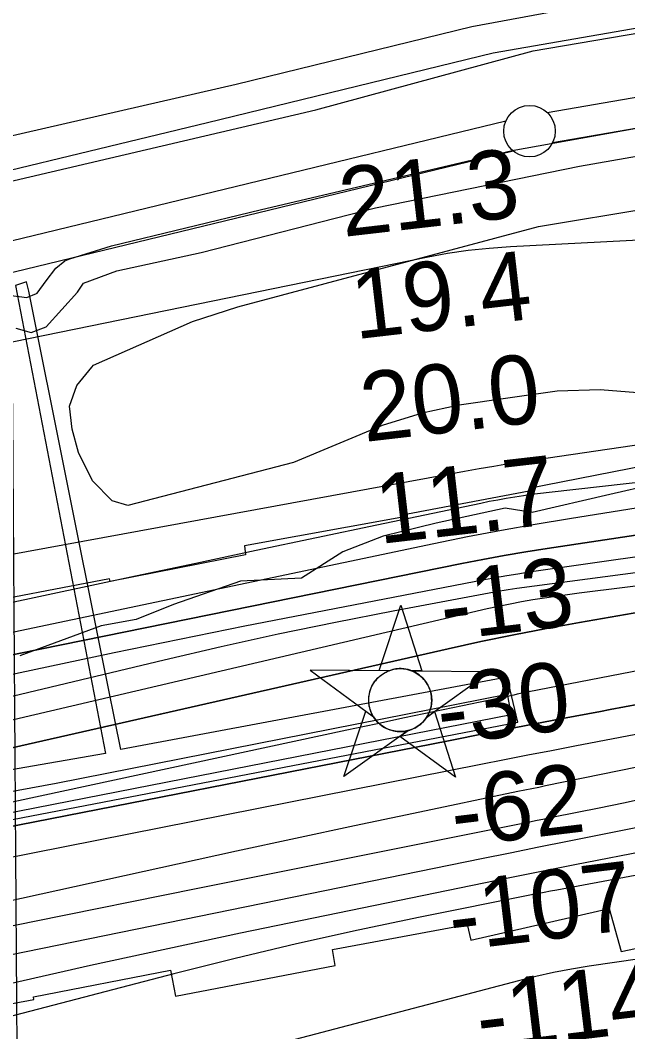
# Model space of a CAD drawing. Extents: x 3508733 to 3546731, y 546897 to 572481.
# Drawn here: x 3518107 to 3518696, y 565606 to 566587 of the extents above; entities that cross this region are included whole.
import ezdxf

# ---------------------------------------------------------------- set-up
doc = ezdxf.new("R2010")
doc.units = 0
for name, color, linetype in [('V-CHAN-DOCK', 7, 'Continuous'), ('V-CHAN-NAID', 7, 'Continuous'), ('V-FLOD-BASE', 7, 'Continuous'), ('V-GRID-MAJR', 7, 'Continuous'), ('V-LEVE-TOET', 7, 'Continuous'), ('V-RIVR-EDGE', 7, 'Continuous'), ('V-RIVR-RANG', 7, 'Continuous'), ('V-ROAD-CNTR', 7, 'Continuous'), ('V-RRAP-RVMT', 7, 'Continuous'), ('V-SITE-STRC', 7, 'Continuous'), ('V-SITE-VEGE', 7, 'Continuous'), ('V-SURV-LINE', 7, 'Continuous'), ('V-TOPO-DPTH', 7, 'Continuous'), ('V-TOPO-MAJR', 7, 'Continuous'), ('V-TOPO-MINR', 7, 'Continuous'), ('V-TOPO-SHOR', 7, 'Continuous'), ('V-TOPO-WATR', 7, 'Continuous')]:
    doc.layers.add(name, color=color, linetype=linetype)

msp = doc.modelspace()

# ---------------------------------------------------------------- linework, layer by layer
at = {"layer": 'V-CHAN-DOCK'}
for points in [[(3518186.52, 565967.83), (3518114.83, 566324.4), (3518112.73, 566333.57), (3518102.12, 566329.91), (3518103.69, 566321.76), (3518189.4, 565876.06), (3518096.29, 565859.93), (3518076.82, 565959.55), (3517887.02, 565919.49), (3517887.88, 565914.27)], [(3517959.44, 565784.97), (3518589.39, 565906.48), (3518579.11, 565950.09), (3518204.17, 565880.03), (3518186.52, 565967.83), (3518114.83, 566324.4), (3518112.73, 566333.57), (3518102.12, 566329.91)], [(3518103.69, 566321.76), (3518189.4, 565876.06), (3518096.29, 565859.93)], [(3517131.86, 565639.29), (3517144.94, 565644.79), (3517155.86, 565644.73), (3517155.88, 565648.11), (3517227.94, 565658.8), (3517227.93, 565657.27), (3517239.93, 565657.2), (3517239.95, 565660.69), (3517311.61, 565672.83), (3517312.53, 565658.83), (3517659.16, 565725.77), (3517657.93, 565735.21), (3517765.2, 565758.26), (3517782.37, 565748.33), (3517807.13, 565753.78), (3517812.95, 565767.98), (3517923.78, 565788.1), (3517926.79, 565778.68), (3517959.44, 565784.97), (3518589.39, 565906.48), (3518579.11, 565950.09), (3518204.17, 565880.03), (3518186.52, 565967.83)]]:
    msp.add_lwpolyline(points, dxfattribs=at)
at = {"layer": 'V-CHAN-NAID'}
for points in [[(3518464.43, 565956.3), (3518454.85, 565956.37), (3518475.97, 566019.86), (3518496.2, 565956.08), (3518486.61, 565956.15), (3518485.03, 565956.73), (3518482.94, 565957.35), (3518480.9, 565957.8), (3518478.86, 565958.1), (3518477.69, 565958.22), (3518476.16, 565958.3), (3518474.44, 565958.3), (3518473.07, 565958.23), (3518471.16, 565958.03), (3518469.8, 565957.81), (3518468.01, 565957.42), (3518466.48, 565957), (3518465.45, 565956.67)], [(3518464.43, 565956.3), (3518387.94, 565956.85), (3518449.51, 565911.45), (3518448.39, 565913.36), (3518447.58, 565914.98), (3518446.76, 565916.95), (3518446.06, 565919.01), (3518445.7, 565920.33), (3518445.34, 565921.96), (3518445.09, 565923.4), (3518444.9, 565925), (3518444.8, 565926.73), (3518444.78, 565928.32), (3518444.89, 565930.39), (3518445.07, 565932.01), (3518445.47, 565934.21), (3518445.95, 565936.13), (3518446.55, 565938.02), (3518447.2, 565939.7), (3518447.93, 565941.29), (3518448.75, 565942.82), (3518449.81, 565944.56), (3518450.84, 565946.03), (3518451.84, 565947.3), (3518452.84, 565948.44), (3518454.15, 565949.78), (3518455.2, 565950.75), (3518456.92, 565952.14), (3518458.13, 565953.01), (3518459.82, 565954.08), (3518461.55, 565955.03), (3518462.99, 565955.71)], [(3518486.61, 565956.15), (3518563.1, 565955.6), (3518500.9, 565911.08), (3518501.81, 565912.57), (3518502.79, 565914.42), (3518503.5, 565916), (3518504.24, 565917.96), (3518504.79, 565919.74), (3518505.18, 565921.38), (3518505.54, 565923.39), (3518505.73, 565924.97), (3518505.85, 565927.17), (3518505.82, 565929.23), (3518505.64, 565931.45), (3518505.37, 565933.21), (3518504.88, 565935.44), (3518504.24, 565937.58), (3518503.49, 565939.57), (3518502.84, 565941.01), (3518501.83, 565942.92), (3518500.77, 565944.65), (3518499.56, 565946.35), (3518498.3, 565947.89), (3518497.03, 565949.25), (3518495.39, 565950.79), (3518493.65, 565952.2), (3518491.97, 565953.37), (3518490.08, 565954.51), (3518488.61, 565955.27)], [(3518482.87, 565898.18), (3518420.66, 565853.65), (3518441.79, 565917.14), (3518449.51, 565911.45), (3518450.14, 565910.48), (3518451.52, 565908.62), (3518452.74, 565907.21), (3518454.2, 565905.71), (3518455.59, 565904.45), (3518457.05, 565903.3), (3518458.45, 565902.31), (3518460.13, 565901.28), (3518461.84, 565900.36), (3518463.63, 565899.55), (3518465.08, 565899), (3518466.71, 565898.47), (3518468.93, 565897.9), (3518470.46, 565897.62), (3518472.49, 565897.36), (3518474.03, 565897.26), (3518475.89, 565897.23), (3518477.58, 565897.31), (3518479.29, 565897.49), (3518481.19, 565897.8)], [(3518500.9, 565911.08), (3518508.69, 565916.66), (3518528.92, 565852.89), (3518475.07, 565892.6), (3518482.87, 565898.18), (3518484.53, 565898.65), (3518486.14, 565899.21), (3518488.3, 565900.13), (3518490.04, 565901.01), (3518491.9, 565902.12), (3518493.64, 565903.34), (3518495.19, 565904.58), (3518496.48, 565905.75), (3518497.87, 565907.17), (3518499.07, 565908.57), (3518500.19, 565910.04)]]:
    msp.add_lwpolyline(points, close=True, dxfattribs=at)
msp.add_circle((3518475.32, 565927.77), 30.54, dxfattribs=at)
at = {"layer": 'V-FLOD-BASE'}
msp.add_lwpolyline([(3518095.45, 566320.82), (3518113.13, 566318.56), (3518122.53, 566322.15), (3518123.12, 566322.74), (3518131.88, 566334.58), (3518141.23, 566347), (3518150.03, 566354.12), (3518154.73, 566355.91), (3518195.29, 566368.52), (3518339.39, 566403.52), (3518584.06, 566460.9), (3518796.46, 566499.24), (3518997.08, 566535.75), (3519002.97, 566536.37), (3519010.62, 566537), (3519058.86, 566547.3)], dxfattribs=at)
at = {"layer": 'V-GRID-MAJR'}
msp.add_spline([(3518190.88, 552332.11), (3518151.22, 558391.11), (3518111.55, 564452.04), (3518071.88, 570512.99), (3518071.87, 570514.91)], degree=3, dxfattribs=at)
at = {"layer": 'V-LEVE-TOET'}
for points in [[(3517635.06, 566318.51), (3517790.52, 566358.34), (3518043.75, 566418.79), (3518393.57, 566500.44), (3518604.36, 566557.69), (3518815.27, 566593.71), (3518991.43, 566623.05), (3519136.95, 566645.72)], [(3518451.29, 566405.29), (3518649.32, 566445.87), (3518756.28, 566464.73), (3518959.03, 566502.97), (3518976.05, 566509.54), (3518987.22, 566510.79), (3518994.89, 566507.89), (3519007.84, 566506.2), (3519020.16, 566511.57), (3519038.38, 566515.79), (3519138.88, 566534.03)], [(3518102.51, 566288.54), (3518117.24, 566284.5), (3518131.92, 566289.88), (3518162.31, 566323.6), (3518168.15, 566332.46), (3518200.43, 566344.41), (3518282.11, 566361.95), (3518451.29, 566405.29)]]:
    msp.add_lwpolyline(points, dxfattribs=at)
at = {"layer": 'V-RIVR-EDGE'}
msp.add_lwpolyline([(3518721.14, 566137.05), (3518678.84, 566127.35), (3518603.43, 566109.77), (3518577.1, 566114.12), (3518510.27, 566099.58), (3518458.77, 566086.84), (3518419.52, 566071.62), (3518379.63, 566045.99), (3518320.19, 566043.07), (3518255.18, 566020.56), (3518219, 566005.94), (3518185.28, 565999.9), (3518106.17, 565970.68)], dxfattribs=at)
at = {"layer": 'V-ROAD-CNTR'}
msp.add_lwpolyline([(3519712.95, 566785.8), (3519437.37, 566738.42), (3518962.97, 566657.35), (3518684.89, 566607.1), (3518544.78, 566581.1), (3518316.18, 566525.03), (3517942.23, 566439.4), (3517865.78, 566419.68)], dxfattribs=at)
at = {"layer": 'V-RRAP-RVMT'}
for points in [[(3519304.25, 566038.12), (3519163.73, 566010.36), (3519164.23, 566005.68), (3519054.87, 565985.48), (3519054.36, 565988.99), (3518927.29, 565964.84), (3518914.72, 566031.29), (3518778.07, 566005.97), (3518747.03, 566161.85), (3518600.25, 566133.12), (3518600.36, 566130.45), (3518475.67, 566106.91)], [(3518475.67, 566106.91), (3518475.97, 566104.92), (3518324.08, 566077.35), (3518325.21, 566068.76), (3518193.96, 566042.75), (3518193.27, 566045.42), (3518047.8, 566017.61)], [(3518678.12, 565725.59), (3518689.72, 565683.99), (3518828.52, 565712.86), (3518827.15, 565719.64), (3518969, 565747.04), (3518967.17, 565756.08), (3519092.65, 565780.26), (3519092.36, 565782.6), (3519217.74, 565805.53), (3519217.3, 565808.96), (3519339.53, 565832.7)], [(3517966.72, 565608.92), (3518119.89, 565637.17), (3518119.39, 565640.05), (3518252.46, 565665.67), (3518257.4, 565640.5), (3518412.16, 565670.2), (3518409.71, 565685.85), (3518540.27, 565710.22), (3518543.71, 565694.73), (3518678.12, 565725.59)]]:
    msp.add_lwpolyline(points, dxfattribs=at)
at = {"layer": 'V-SITE-STRC'}
msp.add_lwpolyline([(3517698.49, 566481.89), (3517714.09, 566359.06), (3517736.82, 566206.81), (3517767.94, 565974.13), (3517795.52, 565783.63), (3518141.36, 565847.09), (3518579.23, 565933.54), (3518582.89, 565913.47), (3517755.53, 565751.49), (3517316.47, 565665.04), (3517315.18, 565685.12), (3517773.1, 565777.59), (3517717.32, 566225.1), (3517685.23, 566458.87), (3517672.42, 566579.91)], dxfattribs=at)
at = {"layer": 'V-SITE-VEGE'}
msp.add_lwpolyline([(3518721.85, 566224.51), (3518669.33, 566228.92), (3518627.46, 566227.5), (3518579.72, 566220.73), (3518532.57, 566213.97), (3518496.64, 566206.09), (3518457.78, 566194.07), (3518371.87, 566158.17), (3518211.09, 566116.54), (3518195.72, 566121.17), (3518176.73, 566140.52), (3518163.01, 566168.16), (3518156.98, 566190.54), (3518154.49, 566212.94), (3518161.45, 566233.04), (3518176.09, 566250.82), (3518177.85, 566252.6), (3518273.75, 566295.04), (3518317.9, 566309.45), (3518609.42, 566387.24), (3518936.47, 566441.65)], dxfattribs=at)
at = {"layer": 'V-SURV-LINE'}
for points in [[(3518617.93, 566497.97), (3519913.1, 566721.77)], [(3519918.21, 566692.21), (3518623.04, 566468.41)], [(3515700.29, 565791.89), (3518577.86, 566489.66)], [(3518584.91, 566460.5), (3515707.35, 565762.73)]]:
    msp.add_lwpolyline(points, dxfattribs=at)
msp.add_circle((3518600.81, 566479.79), 25, dxfattribs=at)
at = {"layer": 'V-TOPO-DPTH'}
for points in [[(3519700.37, 566250.89), (3518619.82, 566129.35), (3518611.48, 566128.35), (3518603.14, 566127.27), (3518594.82, 566126.07), (3518586.51, 566124.8), (3518578.21, 566123.4), (3518569.94, 566121.92), (3518561.68, 566120.33), (3518553.44, 566118.67), (3518452.74, 566097.57), (3518394.17, 566085.26), (3518335.6, 566072.91), (3518277.05, 566060.49), (3518218.51, 566048.03), (3517263.37, 565844.06)], [(3519491.95, 566155.36), (3518588.38, 566036.08), (3518584.29, 566035.5), (3518580.21, 566034.89), (3518576.14, 566034.2), (3518572.07, 566033.47), (3518468.45, 566014.04), (3518412.67, 566003.15), (3518357.01, 565991.72), (3518301.52, 565979.46), (3518246.15, 565966.65), (3517284.92, 565736.79), (3517282.79, 565736.26), (3517280.67, 565735.7), (3517276.45, 565734.49), (3516645.14, 565542.19), (3516518, 565502.59), (3516391.2, 565461.93), (3516264.92, 565419.69), (3516138.99, 565376.39), (3515918.07, 565298.89)], [(3519491.95, 566155.36), (3518588.38, 566036.08), (3518584.29, 566035.5), (3518580.21, 566034.89), (3518576.14, 566034.2), (3518572.07, 566033.47), (3518468.45, 566014.04), (3518412.67, 566003.15), (3518357.01, 565991.72), (3518301.52, 565979.46), (3518246.15, 565966.65), (3517284.92, 565736.79), (3517282.79, 565736.26), (3517280.67, 565735.7), (3517276.45, 565734.49), (3516645.14, 565542.19), (3516518, 565502.59), (3516391.2, 565461.93), (3516264.92, 565419.69), (3516138.99, 565376.39), (3515918.07, 565298.89)], [(3518023.6, 565956.46), (3518534.96, 566060.23), (3518555.62, 566064.25), (3518576.31, 566068.07), (3518597.06, 566071.57), (3518617.85, 566074.86), (3518839.47, 566108.23), (3518971.22, 566127.03), (3519103.14, 566144.46), (3519235.31, 566159.86)], [(3518023.6, 565956.46), (3518534.96, 566060.23), (3518555.62, 566064.25), (3518576.31, 566068.07), (3518597.06, 566071.57), (3518617.85, 566074.86), (3518839.47, 566108.23), (3518971.22, 566127.03), (3519103.14, 566144.46), (3519235.31, 566159.86)], [(3517962.98, 565850.7), (3518521.9, 565977.62), (3518553.63, 565984.57), (3518585.43, 565991.19), (3518617.32, 565997.33), (3518649.28, 566003.14), (3518716.36, 566014.8), (3518781.98, 566025.71), (3518847.69, 566035.96), (3518913.56, 566045.23), (3518979.52, 566053.84), (3519693.8, 566141.68)], [(3517962.98, 565850.7), (3518521.9, 565977.62), (3518553.63, 565984.57), (3518585.43, 565991.19), (3518617.32, 565997.33), (3518649.28, 566003.14), (3518716.36, 566014.8), (3518781.98, 566025.71), (3518847.69, 566035.96), (3518913.56, 566045.23), (3518979.52, 566053.84), (3519693.8, 566141.68)], [(3519340.38, 566066.83), (3519197.82, 566046.36), (3519055.77, 566022.63), (3518914.05, 565996.73), (3518598.63, 565935.36), (3518595.37, 565934.72), (3518592.1, 565934.07), (3518588.84, 565933.4), (3518585.59, 565932.73), (3518535.84, 565922.32), (3518507.72, 565916.41), (3518479.6, 565910.47), (3518451.49, 565904.48), (3518423.39, 565898.47), (3517326.27, 565662.56)], [(3519340.38, 566066.83), (3519197.82, 566046.36), (3519055.77, 566022.63), (3518914.05, 565996.73), (3518598.63, 565935.36), (3518595.37, 565934.72), (3518592.1, 565934.07), (3518588.84, 565933.4), (3518585.59, 565932.73), (3518535.84, 565922.32), (3518507.72, 565916.41), (3518479.6, 565910.47), (3518451.49, 565904.48), (3518423.39, 565898.47), (3517326.27, 565662.56)], [(3518042.98, 565794.59), (3518522, 565888.39), (3518558.9, 565895.58), (3518595.81, 565902.72), (3518632.74, 565909.79), (3518669.68, 565916.81), (3518679.05, 565918.58), (3518720.68, 565926.43), (3518762.32, 565934.26), (3518803.96, 565942.05), (3518845.61, 565949.82), (3518880.86, 565956.38), (3518940.14, 565967.38), (3518999.42, 565978.35), (3519058.72, 565989.27), (3519118.02, 566000.15), (3519303.86, 566034.16)], [(3518042.98, 565794.59), (3518522, 565888.39), (3518558.9, 565895.58), (3518595.81, 565902.72), (3518632.74, 565909.79), (3518669.68, 565916.81), (3518679.05, 565918.58), (3518720.68, 565926.43), (3518762.32, 565934.26), (3518803.96, 565942.05), (3518845.61, 565949.82), (3518880.86, 565956.38), (3518940.14, 565967.38), (3518999.42, 565978.35), (3519058.72, 565989.27), (3519118.02, 566000.15), (3519303.86, 566034.16)]]:
    msp.add_lwpolyline(points, dxfattribs=at)
at = {"layer": 'V-TOPO-MAJR'}
for points in [[(3519540.97, 566043.59), (3519132.21, 565972.87), (3519043.22, 565957.24), (3518954.29, 565941.3), (3518865.44, 565924.91), (3518776.65, 565908.22), (3518644.85, 565883.08), (3518622, 565878.7), (3518599.17, 565874.29), (3518576.34, 565869.83), (3518553.52, 565865.33), (3517807.89, 565717.75)], [(3519318.9, 565880.14), (3519208.46, 565855.43), (3519097.63, 565832.51), (3518986.55, 565810.79), (3518627.11, 565743.51), (3518620.99, 565742.36), (3518614.88, 565741.19), (3518608.77, 565739.99), (3518602.66, 565738.78), (3518494.62, 565717.14), (3518434.61, 565704.58), (3518374.75, 565691.35), (3518315.14, 565677.09), (3518255.68, 565662.15), (3517852.66, 565557.2)]]:
    msp.add_lwpolyline(points, dxfattribs=at)
at = {"layer": 'V-TOPO-MINR'}
for points in [[(3519267.76, 566398.46), (3519122.37, 566393.66), (3518977.04, 566387.57), (3518831.73, 566380.64), (3518582.17, 566367.63), (3518561.73, 566366.1), (3518541.36, 566363.97), (3518521.12, 566360.93), (3518500.95, 566357.28), (3518025.82, 566260.26), (3517885.15, 566229.42), (3517745.16, 566195.9), (3517606.19, 566158.36), (3517467.91, 566118.15), (3517273.51, 566058.57), (3517232.89, 566046.26), (3517192.23, 566034.14), (3517151.49, 566022.28), (3517110.69, 566010.6), (3516571.34, 565858.08), (3516546.13, 565852.59), (3515760.15, 565675.58)], [(3519700.37, 566250.89), (3518619.82, 566129.35), (3518611.48, 566128.35), (3518603.14, 566127.27), (3518594.82, 566126.07), (3518586.51, 566124.8), (3518578.21, 566123.4), (3518569.94, 566121.92), (3518561.68, 566120.33), (3518553.44, 566118.67), (3518452.74, 566097.57), (3518394.17, 566085.26), (3518335.6, 566072.91), (3518277.05, 566060.49), (3518218.51, 566048.03), (3517263.37, 565844.06)], [(3519237.65, 566251.3), (3519105.59, 566233.35), (3518973.63, 566214.61), (3518594.68, 566159.04), (3518580.37, 566156.87), (3518566.08, 566154.59), (3518551.82, 566152.16), (3518537.57, 566149.62), (3517890.32, 566030.84)], [(3519709.36, 566227.85), (3518997.3, 566152.74), (3518926.39, 566144.71), (3518855.57, 566135.94), (3518784.9, 566126.09), (3518714.32, 566115.5), (3518639.41, 566103.68), (3518606.4, 566098.21), (3518573.47, 566092.4), (3518540.62, 566086.1), (3518507.83, 566079.46), (3517549.65, 565877.79)], [(3519751.08, 566168.36), (3518648.83, 566031.41), (3518637.63, 566029.96), (3518626.44, 566028.42), (3518615.26, 566026.76), (3518604.1, 566025.02), (3518592.97, 566023.11), (3518581.87, 566021.03), (3518570.82, 566018.73), (3518559.79, 566016.27), (3517536.66, 565776.71)], [(3519491.95, 566155.36), (3518588.38, 566036.08), (3518584.29, 566035.5), (3518580.21, 566034.89), (3518576.14, 566034.2), (3518572.07, 566033.47), (3518468.45, 566014.04), (3518412.67, 566003.15), (3518357.01, 565991.72), (3518301.52, 565979.46), (3518246.15, 565966.65), (3517284.92, 565736.79), (3517282.79, 565736.26), (3517280.67, 565735.7), (3517276.45, 565734.49), (3516645.14, 565542.19), (3516518, 565502.59), (3516391.2, 565461.93), (3516264.92, 565419.69), (3516138.99, 565376.39), (3515918.07, 565298.89)], [(3519240.5, 566142.01), (3519135.28, 566127.86), (3518600.38, 566051.76), (3518589.49, 566050.13), (3518578.62, 566048.38), (3518567.78, 566046.48), (3518556.96, 566044.46), (3518324.62, 565999.4), (3518197.87, 565973.76), (3518071.42, 565946.78), (3517945.41, 565917.77), (3517819.7, 565887.43), (3517296.21, 565756.62), (3517286.11, 565754.04), (3517276.02, 565751.39), (3517265.96, 565748.65), (3517255.92, 565745.83), (3516959.4, 565661.14), (3516801.55, 565614.57), (3516644.27, 565566.19), (3516487.85, 565515.08), (3516332.01, 565462.17), (3515927.52, 565320.9)], [(3519693.8, 566141.68), (3518979.52, 566053.84), (3518913.56, 566045.23), (3518847.69, 566035.96), (3518781.98, 566025.71), (3518716.36, 566014.8), (3518649.28, 566003.14), (3518617.32, 565997.33), (3518585.43, 565991.19), (3518553.63, 565984.57), (3518521.9, 565977.62), (3517962.98, 565850.7)], [(3519340.38, 566066.83), (3519197.82, 566046.36), (3519055.77, 566022.63), (3518914.05, 565996.73), (3518598.63, 565935.36), (3518595.37, 565934.72), (3518592.1, 565934.07), (3518588.84, 565933.4), (3518585.59, 565932.73), (3518535.84, 565922.32), (3518507.72, 565916.41), (3518479.6, 565910.47), (3518451.49, 565904.48), (3518423.39, 565898.47), (3517326.27, 565662.56)], [(3519303.86, 566034.16), (3519118.02, 566000.15), (3519058.72, 565989.27), (3518999.42, 565978.35), (3518940.14, 565967.38), (3518880.86, 565956.38), (3518845.61, 565949.82), (3518803.96, 565942.05), (3518762.32, 565934.26), (3518720.68, 565926.43), (3518679.05, 565918.58), (3518669.68, 565916.81), (3518632.74, 565909.79), (3518595.81, 565902.72), (3518558.9, 565895.58), (3518522, 565888.39), (3518042.98, 565794.59)], [(3519260.96, 565968.98), (3519128.91, 565946.08), (3518997.19, 565921.36), (3518865.68, 565895.44), (3518616.43, 565844.53), (3518609.72, 565843.15), (3518603.01, 565841.77), (3518596.29, 565840.38), (3518589.58, 565838.98), (3518488.3, 565817.8), (3518430.96, 565805.72), (3518373.66, 565793.51), (3518316.39, 565781.13), (3518259.14, 565768.63), (3517356.59, 565570.07)], [(3519278.05, 565950.81), (3519160.68, 565928.55), (3519043.63, 565904.57), (3518857.25, 565864.25), (3518833.62, 565859.1), (3518810, 565853.9), (3518786.4, 565848.64), (3518762.81, 565843.33), (3518739.21, 565838.06), (3518715.58, 565832.91), (3518691.92, 565827.92), (3518668.23, 565823.04), (3518624.03, 565814.1), (3518615.35, 565812.35), (3518606.68, 565810.61), (3518598.01, 565808.87), (3518589.33, 565807.13), (3518277.47, 565744.83), (3518120.37, 565713.14), (3517963.35, 565681.04)], [(3519260.85, 565925.82), (3519213.25, 565915.32), (3519157.66, 565902.96), (3519102.09, 565890.48), (3519046.57, 565877.81), (3518991.07, 565865.01), (3518935.54, 565852.38), (3518879.94, 565840.09), (3518824.23, 565828.31), (3518768.44, 565816.87), (3518665.22, 565796.21), (3518637.46, 565790.64), (3518609.7, 565785.04), (3518581.96, 565779.42), (3518554.21, 565773.77), (3517716.06, 565602.62)], [(3519290.99, 565904.47), (3519212.89, 565885.88), (3519128.63, 565866.38), (3519044.23, 565847.58), (3518959.59, 565829.82), (3518874.81, 565812.76), (3518644.88, 565767.98), (3518628.68, 565764.8), (3518612.47, 565761.58), (3518596.28, 565758.32), (3518580.1, 565755.03), (3518320.43, 565701.76), (3518174.75, 565670.41), (3518029.52, 565637.18)], [(3519286.14, 565829.24), (3519205.33, 565808.7), (3519196.46, 565801.6), (3519191.97, 565793.86), (3519194.08, 565785.17), (3519200.58, 565775.84), (3519206.2, 565767.35), (3519207.8, 565759.65), (3519203.38, 565753.14), (3519194.94, 565747.43), (3518658.73, 565669.53), (3518641.39, 565666.71), (3518624.13, 565663.5), (3518606.98, 565659.71), (3518589.92, 565655.53), (3518329.01, 565586.93)]]:
    msp.add_lwpolyline(points, dxfattribs=at)
at = {"layer": 'V-TOPO-SHOR'}
msp.add_lwpolyline([(3517658.04, 566336.42), (3517971.92, 566411.96), (3518288.16, 566488.11), (3518565.53, 566555.78), (3518904.83, 566615.01)], dxfattribs=at)
at = {"layer": 'V-TOPO-WATR'}
msp.add_lwpolyline([(3519235.31, 566159.86), (3519103.14, 566144.46), (3518971.22, 566127.03), (3518839.47, 566108.23), (3518617.85, 566074.86), (3518597.06, 566071.57), (3518576.31, 566068.07), (3518555.62, 566064.25), (3518534.96, 566060.23), (3518023.6, 565956.46)], dxfattribs=at)

# ---------------------------------------------------------------- texts
at = {"layer": 'V-RIVR-RANG'}
for s, rotation, p in [('21.3', 6.58833, (3518420.19, 566377.13)), ('19.4', 6.58833, (3518431.91, 566277.82)), ('20.0', 6.58833, (3518440.75, 566178.18)), ('11.7', 6.58833, (3518455.36, 566079.2)), ('-13', 6.87461, (3518517.86, 565985.42)), ('-30', 6.87461, (3518514.66, 565884.3)), ('-62', 6.87461, (3518528.22, 565785.22)), ('-107', 6.87461, (3518526.05, 565684.23)), ('-114', 6.87461, (3518552.97, 565586.75))]:
    msp.add_text(s, height=67, rotation=rotation, dxfattribs=at).set_placement(p)

doc.saveas('drawing.dxf')
